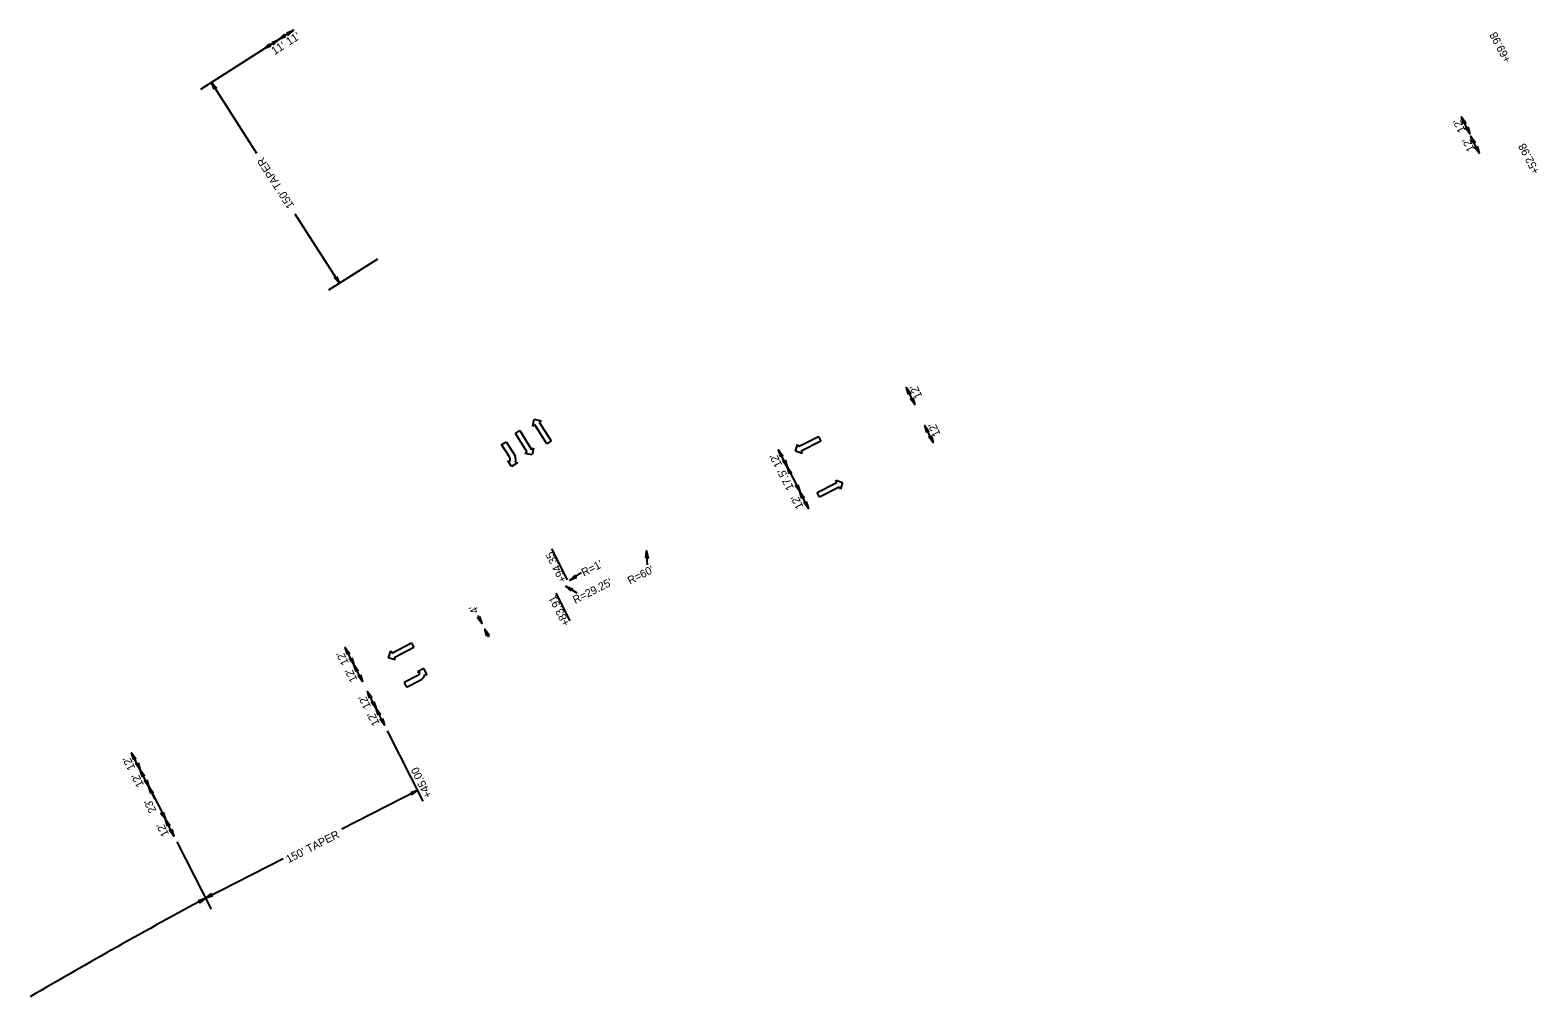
# Model space of a CAD drawing. Extents: x 2320991 to 2332664, y 598057 to 612602.
# Drawn here: x 2331714 to 2332664, y 611993 to 612602 of the extents above; entities that cross this region are included whole.
import ezdxf

# ---------------------------------------------------------------- set-up
doc = ezdxf.new("R2010")
doc.units = 0
for name, color, linetype in [('Prop Dimension', 7, 'Continuous'), ('Prop Dimension Text', 7, 'Continuous'), ('Prop Horizontal Alignment Tick Small', 7, 'Continuous'), ('Prop Lane Arrow CELL', 7, 'Continuous'), ('Prop Terminator CELL', 7, 'Continuous')]:
    doc.layers.add(name, color=color, linetype=linetype)

msp = doc.modelspace()

# ---------------------------------------------------------------- linework, layer by layer
at = {"layer": 'Prop Dimension'}
for p, q in [((2331879.59, 612602.06), (2331870.31, 612596.14)), ((2331870.31, 612596.14), (2331861.04, 612590.23)), ((2331861.04, 612590.23), (2331820.95, 612564.66)), ((2331856.38, 612524.34), (2331827.86, 612569.06)), ((2332620.96, 612536.7), (2332615.7, 612547.48)), ((2332626.86, 612524.49), (2332621.6, 612535.28)), ((2331908.51, 612442.59), (2331880.73, 612486.16)), ((2331932.42, 612457.84), (2331901.61, 612438.19)), ((2332271.13, 612366.14), (2332265.87, 612376.92)), ((2332282.67, 612342.24), (2332277.41, 612353.03)), ((2332190.77, 612326.96), (2332185.33, 612337.65)), ((2332190.77, 612326.96), (2332198.7, 612311.36)), ((2332204.14, 612300.66), (2332198.7, 612311.36)), ((2332052.36, 612255.75), (2332042.47, 612275.2)), ((2332102.71, 612265.13), (2332102.08, 612273.96)), ((2332053.68, 612255.36), (2332061.17, 612260.36)), ((2332051.16, 612251.78), (2332058.21, 612247.5)), ((2332044.86, 612247.46), (2332053.75, 612229.97)), ((2331995.74, 612233.2), (2331998.26, 612228.25)), ((2332000.07, 612224.69), (2332002.58, 612219.75)), ((2331917.64, 612202.34), (2331912.2, 612213.04)), ((2331923.07, 612191.64), (2331917.64, 612202.34)), ((2331931.6, 612174.8), (2331926.16, 612185.5)), ((2331937.03, 612164.11), (2331931.6, 612174.8)), ((2331961.33, 612116.3), (2331938.85, 612160.54)), ((2331782.96, 612136.11), (2331777.52, 612146.81)), ((2331788.4, 612125.42), (2331782.96, 612136.11)), ((2331788.37, 612125.48), (2331798.8, 612104.98)), ((2331909.95, 612098.86), (2331957.81, 612123.19)), ((2331804.24, 612094.29), (2331798.8, 612104.98)), ((2331806.05, 612090.72), (2331827.61, 612048.32)), ((2331824.1, 612055.22), (2331873.1, 612080.13))]:
    msp.add_line(p, q, dxfattribs=at)
msp.add_arc((2333579.32, 608805.62), 3693.33, 118.37497, 120.34199, dxfattribs=at)
at = {"layer": 'Prop Horizontal Alignment Tick Small'}
msp.add_line((2331792.36, 612117.62), (2331790.1, 612122.07), dxfattribs=at)
at = {"layer": 'Prop Lane Arrow CELL'}
for p, q in [((2332030.4, 612352.58), (2332031.33, 612356.9)), ((2332031.66, 612353.38), (2332030.4, 612352.58)), ((2332031.33, 612356.9), (2332035.72, 612355.95)), ((2332039.16, 612341.55), (2332031.66, 612353.38)), ((2332035.72, 612355.95), (2332034.45, 612355.15)), ((2332034.45, 612355.15), (2332041.95, 612343.32)), ((2332019.4, 612348), (2332022.19, 612349.77)), ((2332026.89, 612336.18), (2332019.4, 612348)), ((2332022.19, 612349.77), (2332029.68, 612337.94)), ((2332197.94, 612339.7), (2332210.4, 612346.09)), ((2332210.4, 612346.09), (2332211.9, 612343.15)), ((2332010.78, 612340.95), (2332013.56, 612342.73)), ((2332015.7, 612333.24), (2332010.78, 612340.95)), ((2332013.56, 612342.73), (2332019.23, 612333.83)), ((2332025.63, 612335.37), (2332026.89, 612336.18)), ((2332030.02, 612334.43), (2332025.63, 612335.37)), ((2332029.68, 612337.94), (2332030.95, 612338.75)), ((2332030.95, 612338.75), (2332030.02, 612334.43)), ((2332041.95, 612343.32), (2332039.16, 612341.55)), ((2332195.91, 612336.75), (2332197.26, 612341.04)), ((2332200.13, 612335.43), (2332195.91, 612336.75)), ((2332197.26, 612341.04), (2332197.94, 612339.7)), ((2332211.9, 612343.15), (2332199.45, 612336.77)), ((2332199.45, 612336.77), (2332200.13, 612335.43)), ((2332017.08, 612327.07), (2332014.62, 612330.83)), ((2332014.62, 612330.83), (2332016.07, 612330.51)), ((2332020.77, 612329.48), (2332017.08, 612327.07)), ((2332019.32, 612329.8), (2332020.77, 612329.48)), ((2332209.61, 612310.8), (2332222.1, 612317.13)), ((2332222.1, 612317.13), (2332221.42, 612318.47)), ((2332221.42, 612318.47), (2332225.63, 612317.13)), ((2332225.63, 612317.13), (2332224.27, 612312.85)), ((2332211.11, 612307.85), (2332209.61, 612310.8)), ((2332223.59, 612314.19), (2332211.11, 612307.85)), ((2332224.27, 612312.85), (2332223.59, 612314.19)), ((2331939.53, 612206.67), (2331940.87, 612210.95)), ((2331940.87, 612210.95), (2331941.56, 612209.62)), ((2331941.56, 612209.62), (2331954.01, 612216.01)), ((2331955.52, 612213.07), (2331943.06, 612206.68)), ((2331954.01, 612216.01), (2331955.52, 612213.07)), ((2331943.75, 612205.34), (2331939.53, 612206.67)), ((2331943.06, 612206.68), (2331943.75, 612205.34)), ((2331957.45, 612195.26), (2331949.28, 612191.13)), ((2331950.78, 612188.18), (2331960.19, 612192.95)), ((2331961.78, 612199.87), (2331957.75, 612197.88)), ((2331957.75, 612197.88), (2331959.16, 612197.42)), ((2331963.73, 612195.92), (2331961.78, 612199.87)), ((2331962.32, 612196.39), (2331963.73, 612195.92)), ((2331949.28, 612191.13), (2331950.78, 612188.18))]:
    msp.add_line(p, q, dxfattribs=at)
for centre, radius, start, end in [((2332012.96, 612331.48), 3.27, 342.87696, 32.53513), ((2332014.44, 612331.72), 5.25, 338.54737, 23.85906), ((2331955.98, 612198.17), 3.27, 296.87044, 346.52861), ((2331957.14, 612197.21), 5.25, 305.54651, 350.85821)]:
    msp.add_arc(centre, radius, start, end, dxfattribs=at)
at = {"layer": 'Prop Terminator CELL'}
for points in [[(2331875.38, 612600.29), (2331879.59, 612602.06), (2331876.2, 612598.95), (2331876.26, 612599.93)], [(2331865.25, 612591.99), (2331861.04, 612590.23), (2331864.42, 612593.33), (2331864.37, 612592.35)], [(2331866.1, 612594.37), (2331870.31, 612596.14), (2331866.93, 612593.03), (2331866.98, 612594.02)], [(2331874.53, 612597.91), (2331870.31, 612596.14), (2331873.7, 612599.25), (2331873.64, 612598.26)], [(2331829.62, 612564.85), (2331827.86, 612569.06), (2331830.96, 612565.68), (2331829.98, 612565.73)], [(2332616.98, 612543.1), (2332615.7, 612547.48), (2332618.4, 612543.77), (2332617.43, 612543.93)], [(2332619.68, 612541.08), (2332620.96, 612536.7), (2332618.26, 612540.41), (2332619.23, 612540.25)], [(2332622.88, 612530.89), (2332621.6, 612535.28), (2332624.3, 612531.56), (2332623.33, 612531.73)], [(2332625.58, 612528.88), (2332626.86, 612524.49), (2332624.16, 612528.21), (2332625.13, 612528.04)], [(2331906.75, 612446.8), (2331908.51, 612442.59), (2331905.41, 612445.98), (2331906.39, 612445.92)], [(2332267.15, 612372.54), (2332265.87, 612376.92), (2332268.58, 612373.21), (2332267.6, 612373.37)], [(2332269.86, 612370.52), (2332271.13, 612366.14), (2332268.43, 612369.85), (2332269.4, 612369.69)], [(2332278.69, 612348.65), (2332277.41, 612353.03), (2332280.11, 612349.31), (2332279.14, 612349.48)], [(2332281.4, 612346.63), (2332282.67, 612342.24), (2332279.97, 612345.96), (2332280.94, 612345.79)], [(2332186.68, 612333.29), (2332185.33, 612337.65), (2332188.09, 612333.98), (2332187.12, 612334.13)], [(2332189.42, 612331.32), (2332190.77, 612326.96), (2332188, 612330.63), (2332188.98, 612330.48)], [(2332192.12, 612322.59), (2332190.77, 612326.96), (2332193.53, 612323.28), (2332192.56, 612323.43)], [(2332197.35, 612315.72), (2332198.7, 612311.36), (2332195.93, 612315.03), (2332196.91, 612314.88)], [(2332200.05, 612306.99), (2332198.7, 612311.36), (2332201.46, 612307.68), (2332200.49, 612307.83)], [(2332202.79, 612305.02), (2332204.14, 612300.66), (2332201.37, 612304.33), (2332202.35, 612304.18)], [(2332101.63, 612269.42), (2332102.08, 612273.96), (2332103.2, 612269.5), (2332102.36, 612270.02)], [(2332057.85, 612257.21), (2332053.68, 612255.36), (2332057, 612258.54), (2332056.96, 612257.55)], [(2332054.61, 612248.78), (2332051.16, 612251.78), (2332055.45, 612250.11), (2332054.54, 612249.73)], [(2331996.91, 612232.62), (2331998.26, 612228.25), (2331995.5, 612231.92), (2331996.47, 612231.77)], [(2332001.42, 612220.32), (2332000.07, 612224.69), (2332002.84, 612221.02), (2332001.86, 612221.17)], [(2331913.55, 612208.68), (2331912.2, 612213.04), (2331914.96, 612209.37), (2331913.99, 612209.52)], [(2331916.29, 612206.7), (2331917.64, 612202.34), (2331914.87, 612206.01), (2331915.85, 612205.86)], [(2331918.99, 612197.98), (2331917.64, 612202.34), (2331920.4, 612198.67), (2331919.43, 612198.82)], [(2331921.73, 612196.01), (2331923.07, 612191.64), (2331920.31, 612195.32), (2331921.28, 612195.17)], [(2331927.51, 612181.14), (2331926.16, 612185.5), (2331928.92, 612181.83), (2331927.95, 612181.98)], [(2331930.25, 612179.17), (2331931.6, 612174.8), (2331928.83, 612178.47), (2331929.81, 612178.32)], [(2331932.94, 612170.44), (2331931.6, 612174.8), (2331934.36, 612171.13), (2331933.39, 612171.28)], [(2331935.68, 612168.47), (2331937.03, 612164.11), (2331934.27, 612167.78), (2331935.24, 612167.63)], [(2331778.87, 612142.45), (2331777.52, 612146.81), (2331780.29, 612143.14), (2331779.31, 612143.29)], [(2331781.61, 612140.48), (2331782.96, 612136.11), (2331780.2, 612139.79), (2331781.17, 612139.63)], [(2331784.31, 612131.75), (2331782.96, 612136.11), (2331785.73, 612132.44), (2331784.75, 612132.59)], [(2331787.05, 612129.78), (2331788.4, 612125.42), (2331785.64, 612129.09), (2331786.61, 612128.94)], [(2331789.72, 612121.12), (2331788.37, 612125.48), (2331791.14, 612121.81), (2331790.16, 612121.96)], [(2331953.45, 612121.84), (2331957.81, 612123.19), (2331954.14, 612120.43), (2331954.29, 612121.4)], [(2331797.45, 612109.34), (2331798.8, 612104.98), (2331796.03, 612108.65), (2331797.01, 612108.5)], [(2331800.15, 612100.62), (2331798.8, 612104.98), (2331801.56, 612101.31), (2331800.59, 612101.46)], [(2331802.89, 612098.65), (2331804.24, 612094.29), (2331801.47, 612097.96), (2331802.45, 612097.81)], [(2331819.8, 612053.69), (2331824.1, 612055.22), (2331820.55, 612052.3), (2331820.66, 612053.28)], [(2331828.46, 612056.57), (2331824.1, 612055.22), (2331827.77, 612057.98), (2331827.62, 612057.01)]]:
    msp.add_lwpolyline(points, close=True, dxfattribs=at)

# ---------------------------------------------------------------- texts
at = {"layer": 'Prop Dimension'}
for s, rotation, p in [('+94.35', 116.94705, (2332052.01, 612255.6)), ('+83.91', 116.94705, (2332053.94, 612228.13)), ('+45.00', 116.16822, (2331966.92, 612119.8))]:
    msp.add_text(s, height=5, rotation=rotation, dxfattribs=at).set_placement(p)
at = {"layer": 'Prop Dimension Text'}
for s, rotation, p in [("11'", 32.52855, (2331876.87, 612592.23)), ('+69.98', 117.59923, (2332647.14, 612583.19)), ("11'", 32.52855, (2331867.6, 612586.32)), ("12'", 115.99169, (2332618.33, 612538.94)), ("12'", 115.99169, (2332624.23, 612526.91)), ('+52.98', 117.59923, (2332665.23, 612512.99)), ("150' TAPER", 122.61403, (2331880.22, 612491.6)), ("12'", 115.99169, (2332276.06, 612371.37)), ("12'", 115.99169, (2332287.6, 612347.48)), ("12'", 116.94653, (2332187.78, 612328.13)), ("17.5'", 116.94653, (2332195.14, 612313.66)), ("12'", 116.94653, (2332201.15, 612301.83)), ("R=1'", 26.94705, (2332062.61, 612257.79)), ("R=60'", 26.94705, (2332091.67, 612252.67)), ("R=29.25'", 26.94705, (2332057.15, 612240.52)), ("4'", 116.94653, (2331996.54, 612235.92)), ("12'", 116.94653, (2331914.65, 612203.51)), ("12'", 116.94653, (2331920.09, 612192.82)), ("12'", 116.94653, (2331928.61, 612175.97)), ("12'", 116.94653, (2331934.05, 612165.28)), ("12'", 116.94653, (2331779.98, 612137.28)), ("12'", 116.94653, (2331785.42, 612126.59)), ("23'", 116.94653, (2331793.35, 612110.37)), ("12'", 116.94653, (2331801.25, 612095.46)), ("150' TAPER", 26.94705, (2331876.39, 612077.15))]:
    msp.add_text(s, height=5, rotation=rotation, dxfattribs=at).set_placement(p)

doc.saveas('drawing.dxf')
